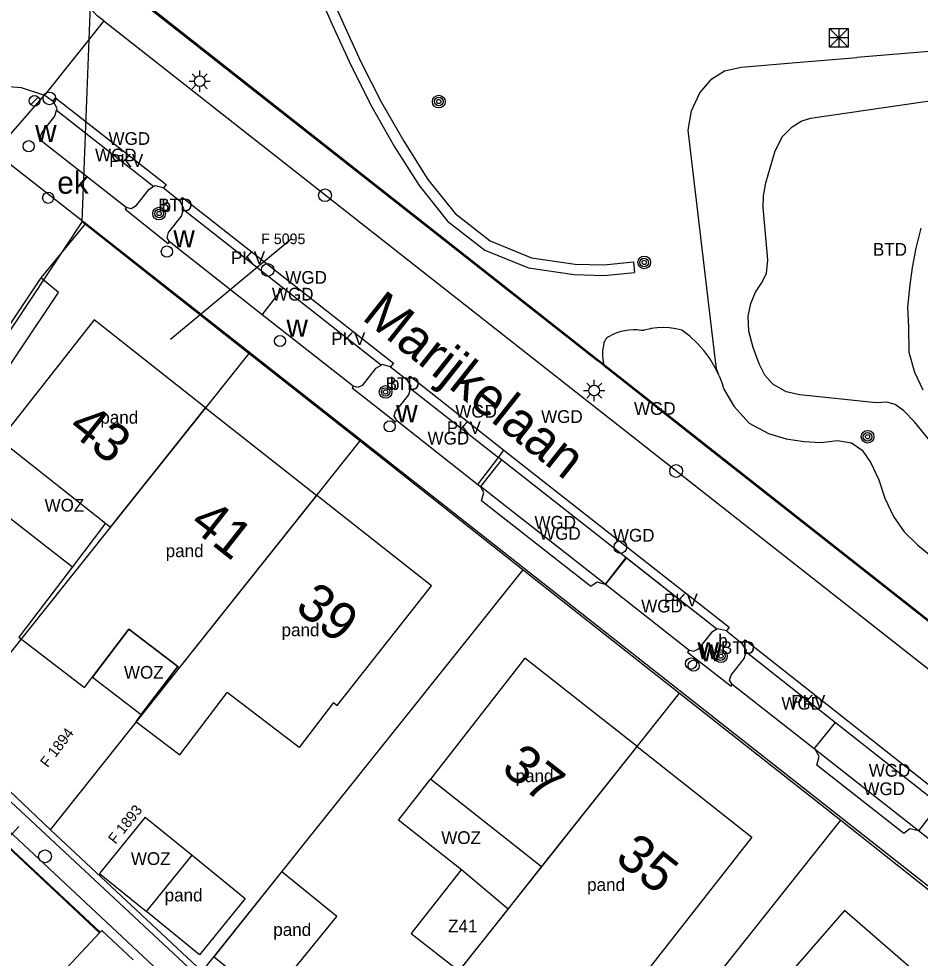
# Model space of a CAD drawing. Extents: x 198240 to 198429, y 356553 to 356721.
# Drawn here: x 198284.19 to 198326.68, y 356585.33 to 356629.62 of the extents above; entities that cross this region are included whole.
import ezdxf

# ---------------------------------------------------------------- set-up
doc = ezdxf.new("R2010")
doc.units = 0
for name, color, linetype in [('Afsluitpaal', 7, 'Continuous'), ('begroeid terreindeel kenmerkpunt', 7, 'Continuous'), ('bijgebouw', 7, 'Continuous'), ('bijpijling', 7, 'Continuous'), ('BOOM', 7, 'Continuous'), ('Elektrakast', 7, 'Continuous'), ('grens individueel parkeervak', 7, 'Continuous'), ('Grens maaiveld', 7, 'Continuous'), ('grens WOZ object', 7, 'Continuous'), ('hoofdgebouw', 7, 'Continuous'), ('huisnummerreeks BGT', 7, 'Continuous'), ('identificerend kenmerkpunt bijpand', 7, 'Continuous'), ('identificerend kenmerkpunt pand', 7, 'Continuous'), ('identificerend kenmerkpunt parkeervak', 7, 'Continuous'), ('identificerend kenmerkpunt WOZ object', 7, 'Continuous'), ('kant verharding', 7, 'Continuous'), ('kolk', 7, 'Continuous'), ('LICHTMAST', 7, 'Continuous'), ('openbare ruimte label tekst', 7, 'Continuous'), ('Perceelnummer', 7, 'Continuous'), ('perceelsgrens_definitief', 7, 'Continuous'), ('schutting geen IMGeo', 7, 'Continuous'), ('Speelvoorziening', 7, 'Continuous'), ('tussenmuur', 7, 'Continuous'), ('tussenmuur bijgebouw (GBKN Zuid)', 7, 'Continuous'), ('vlakafsluiter', 7, 'Continuous'), ('waterleidingput', 7, 'Continuous'), ('wegdeel kenmerkpunt', 7, 'Continuous'), ('weginrichtingselement', 7, 'Continuous'), ('weginrichtingselement lijn', 7, 'Continuous')]:
    doc.layers.add(name, color=color, linetype=linetype)

msp = doc.modelspace()

# ---------------------------------------------------------------- linework, layer by layer
at = {"layer": 'Afsluitpaal'}
msp.add_line((198285.105, 356625.932), (198284.755, 356625.575), dxfattribs=at)
msp.add_circle((198284.932, 356625.752), 0.25, dxfattribs=at)
at = {"layer": 'bijgebouw'}
for p, q in [((198290.208, 356587.525), (198292.365, 356590.18)), ((198307.263, 356587.645), (198305.057, 356589.501)), ((198288.036, 356586.564), (198288.004, 356586.53))]:
    msp.add_line(p, q, dxfattribs=at)
for points in [[(198292.365, 356590.18), (198294.863, 356588.151), (198292.706, 356585.496), (198290.208, 356587.525)], [(198304.895, 356584.747), (198302.686, 356586.482), (198305.057, 356589.501)], [(198293.396, 356585.4), (198295.948, 356583.327), (198299.176, 356587.3), (198296.591, 356589.4)], [(198304.895, 356584.747), (198304.94, 356584.712), (198307.038, 356587.361)], [(198288.004, 356586.53), (198286.046, 356584.433), (198287.524, 356583.052)], [(198289.586, 356585.259), (198288.107, 356586.64), (198288.036, 356586.564)]]:
    msp.add_lwpolyline(points, dxfattribs=at)
at = {"layer": 'bijpijling'}
for points in [[(198291.34, 356614.512), (198297.037, 356619.245)], [(198284.2, 356591.537), (198281.985, 356589.12)]]:
    msp.add_lwpolyline(points, dxfattribs=at)
at = {"layer": 'BOOM'}
for centre, radius in [((198303.989, 356625.719), 0.3), ((198303.989, 356625.719), 0.2), ((198303.989, 356625.719), 0.1), ((198290.807, 356620.438), 0.3), ((198290.807, 356620.438), 0.2), ((198290.807, 356620.438), 0.1), ((198313.67, 356618.133), 0.3), ((198313.67, 356618.133), 0.2), ((198313.67, 356618.133), 0.1), ((198301.481, 356612.027), 0.3), ((198301.481, 356612.027), 0.2), ((198301.481, 356612.027), 0.1), ((198324.194, 356609.914), 0.3), ((198324.194, 356609.914), 0.2), ((198324.194, 356609.914), 0.1), ((198317.286, 356599.569), 0.3), ((198317.286, 356599.569), 0.2), ((198317.286, 356599.569), 0.1)]:
    msp.add_circle(centre, radius, dxfattribs=at)
at = {"layer": 'Elektrakast'}
msp.add_circle((198285.578, 356621.181), 0.263, dxfattribs=at)
msp.add_circle((198285.578, 356621.181), 0.263, dxfattribs=at)
at = {"layer": 'grens individueel parkeervak'}
for p, q in [((198295.667, 356615.664), (198296.651, 356616.938)), ((198305.835, 356607.67), (198306.799, 356608.938)), ((198312.797, 356604.22), (198311.822, 356602.963)), ((198317.094, 356600.839), (198312.797, 356604.22)), ((198321.677, 356595.203), (198322.687, 356596.444)), ((198327.572, 356592.592), (198326.591, 356591.338))]:
    msp.add_line(p, q, dxfattribs=at)
at = {"layer": 'Grens maaiveld'}
for p, q in [((198288.208, 356629.517), (198285.402, 356626.015)), ((198311.777, 356613.258), (198311.48, 356613.492)), ((198317.199, 356612.779), (198317.078, 356613.123)), ((198306.799, 356608.938), (198307.06, 356609.283)), ((198306.942, 356608.825), (198305.958, 356607.573)), ((198306.942, 356608.825), (198306.799, 356608.938)), ((198312.797, 356604.22), (198306.942, 356608.825)), ((198311.849, 356602.941), (198312.832, 356604.192)), ((198312.832, 356604.192), (198312.797, 356604.22)), ((198317.094, 356600.839), (198312.832, 356604.192))]:
    msp.add_line(p, q, dxfattribs=at)
for points in [[(198336.899, 356626.798), (198336.881, 356626.857), (198336.843, 356627.128), (198336.681, 356627.641), (198336.15, 356628.206), (198335.359, 356628.591), (198334.475, 356628.685), (198323.691, 356627.793)], [(198285.813, 356625.732), (198285.921, 356625.893), (198291.141, 356621.811), (198291.01, 356621.645)], [(198291.791, 356621.031), (198291.917, 356621.197), (198301.847, 356613.38), (198301.714, 356613.215)], [(198317.199, 356612.779), (198316.997, 356613.202), (198316.756, 356613.605), (198316.478, 356613.982), (198316.164, 356614.331), (198315.819, 356614.649), (198315.446, 356614.933), (198315.158, 356615.005), (198314.865, 356615.05), (198314.568, 356615.065), (198314.272, 356615.052), (198313.983, 356615.011), (198313.978, 356615.01), (198313.976, 356615.01), (198313.949, 356615.003), (198313.69, 356614.94), (198313.664, 356614.934), (198313.638, 356614.929), (198313.612, 356614.926), (198313.585, 356614.925), (198313.559, 356614.926), (198313.533, 356614.929), (198313.338, 356614.948), (198313.142, 356614.952), (198312.946, 356614.94), (198312.752, 356614.912), (198312.56, 356614.869), (198312.373, 356614.81), (198312.192, 356614.736), (198312.016, 356614.648), (198311.979, 356614.625), (198311.944, 356614.6), (198311.911, 356614.571), (198311.881, 356614.54), (198311.853, 356614.507), (198311.829, 356614.471), (198311.807, 356614.434), (198311.788, 356614.394), (198311.773, 356614.354), (198311.761, 356614.312), (198311.727, 356614.138), (198311.707, 356613.961), (198311.703, 356613.784), (198311.705, 356613.744), (198311.713, 356613.607), (198311.738, 356613.431), (198311.777, 356613.258)], [(198311.777, 356613.258), (198312.501, 356612.688), (198316.479, 356609.557), (198334.051, 356595.726), (198335.895, 356595.044), (198338.762, 356595.561)], [(198302.5, 356612.597), (198302.634, 356612.765), (198307.06, 356609.283)], [(198317.199, 356612.779), (198317.336, 356612.425), (198317.386, 356612.247), (198317.407, 356612.187), (198317.895, 356611.359), (198318.614, 356610.555), (198319.52, 356610.06), (198320.357, 356609.822), (198321.201, 356609.69), (198321.995, 356609.641), (198322.783, 356609.732), (198323.445, 356609.626), (198323.947, 356609.289), (198324.35, 356608.68), (198324.73, 356607.89), (198325.01, 356607.025), (198325.417, 356606.155), (198325.926, 356605.432), (198326.545, 356604.821), (198327.369, 356604.143), (198328.198, 356603.565), (198329.158, 356603.295), (198329.827, 356603.248)], [(198307.06, 356609.283), (198317.674, 356600.934), (198317.546, 356600.763)], [(198318.292, 356600.168), (198318.429, 356600.335), (198329.434, 356591.655)], [(198313.331, 356595.307), (198318.74, 356591.044), (198314.299, 356585.364), (198312.495, 356583.057)], [(198328.26, 356583.099), (198323.101, 356587.58), (198317.022, 356580.581)]]:
    msp.add_lwpolyline(points, dxfattribs=at)
at = {"layer": 'grens WOZ object'}
for p, q in [((198283.799, 356606.053), (198286.719, 356603.776)), ((198289.384, 356600.837), (198287.66, 356598.573)), ((198291.689, 356599.081), (198289.384, 356600.837)), ((198289.966, 356596.817), (198291.689, 356599.081)), ((198287.66, 356598.573), (198289.966, 356596.817)), ((198302.092, 356591.83), (198303.592, 356593.774)), ((198290.157, 356591.974), (198288, 356589.319)), ((198290.157, 356591.974), (198292.365, 356590.18)), ((198305.057, 356589.501), (198302.092, 356591.83)), ((198307.263, 356587.645), (198308.835, 356589.63)), ((198288, 356589.319), (198290.208, 356587.525))]:
    msp.add_line(p, q, dxfattribs=at)
at = {"layer": 'hoofdgebouw'}
for p, q in [((198287.746, 356615.433), (198283.304, 356609.78)), ((198293.001, 356611.274), (198287.746, 356615.433)), ((198293.001, 356611.274), (198298.237, 356607.149)), ((198283.398, 356609.706), (198288.287, 356605.835)), ((198288.287, 356605.835), (198286.719, 356603.776)), ((198308.835, 356589.63), (198303.592, 356593.774)), ((198307.038, 356587.361), (198307.263, 356587.645))]:
    msp.add_line(p, q, dxfattribs=at)
for points in [[(198299.019, 356597.382), (198299.195, 356597.243), (198303.641, 356602.893), (198298.237, 356607.149)], [(198286.719, 356603.776), (198284.195, 356600.459), (198287.298, 356598.097), (198289.384, 356600.837), (198291.689, 356599.081)], [(198313.331, 356595.307), (198308.042, 356599.476), (198303.592, 356593.774)], [(198291.689, 356599.081), (198289.712, 356596.484), (198291.776, 356594.912), (198294.017, 356597.856)], [(198299.019, 356597.382), (198297.412, 356595.271), (198294.017, 356597.856)]]:
    msp.add_lwpolyline(points, dxfattribs=at)
at = {"layer": 'kant verharding'}
for p, q in [((198288.208, 356629.517), (198332.081, 356595.014)), ((198320.826, 356627.555), (198323.691, 356627.793)), ((198285.978, 356625.317), (198290.565, 356621.72)), ((198287.334, 356619.961), (198283.058, 356623.324)), ((198291.01, 356621.645), (198291.791, 356621.031)), ((198291.956, 356620.634), (198296.651, 356616.938)), ((198295.667, 356615.664), (198291.298, 356619.105)), ((198313.171, 356618.156), (198313.219, 356617.658)), ((198285.231, 356617.401), (198277.829, 356606.337)), ((198296.651, 356616.938), (198301.281, 356613.294)), ((198299.953, 356612.296), (198295.667, 356615.664)), ((198317.078, 356613.123), (198316.972, 356614.011)), ((198301.714, 356613.215), (198302.5, 356612.597)), ((198302.661, 356612.193), (198306.799, 356608.938)), ((198302.003, 356610.682), (198305.835, 356607.67)), ((198305.835, 356607.67), (198305.958, 356607.573)), ((198311.822, 356602.963), (198305.958, 356607.573)), ((198311.849, 356602.941), (198311.822, 356602.963)), ((198315.775, 356599.854), (198311.849, 356602.941)), ((198317.546, 356600.763), (198318.292, 356600.168)), ((198318.467, 356599.771), (198322.687, 356596.444)), ((198321.677, 356595.203), (198317.813, 356598.241)), ((198322.687, 356596.444), (198327.572, 356592.592)), ((198321.742, 356595.152), (198321.677, 356595.203)), ((198326.591, 356591.338), (198321.742, 356595.152)), ((198288.036, 356586.564), (198281.792, 356592.387))]:
    msp.add_line(p, q, dxfattribs=at)
for points in [[(198296.093, 356639.541), (198296.614, 356637.469), (198297.244, 356635.408), (198297.875, 356633.478), (198298.543, 356631.541), (198299.422, 356629.562), (198300.306, 356627.615), (198301.275, 356625.709), (198302.334, 356623.845), (198303.469, 356622.044), (198304.754, 356620.44), (198306.413, 356619.147), (198308.355, 356618.357), (198310.417, 356618.058), (198311.77, 356618.022), (198313.171, 356618.156)], [(198295.609, 356639.419), (198296.132, 356637.335), (198296.768, 356635.258), (198297.401, 356633.318), (198298.077, 356631.357), (198298.966, 356629.358), (198299.856, 356627.399), (198300.835, 356625.473), (198301.904, 356623.589), (198303.061, 356621.754), (198304.4, 356620.082), (198306.161, 356618.711), (198308.223, 356617.871), (198310.375, 356617.558), (198311.788, 356617.522), (198313.219, 356617.658)], [(198288.971, 356634.577), (198289.364, 356630.899), (198311.48, 356613.492)], [(198288.208, 356629.517), (198287.888, 356629.764), (198286.69, 356631.104)], [(198316.972, 356614.011), (198315.738, 356624.363), (198315.902, 356625.288), (198316.294, 356626.134), (198316.86, 356626.789), (198317.445, 356627.16), (198318.234, 356627.341), (198320.826, 356627.555)], [(198276.992, 356622.565), (198277.573, 356623.379), (198278.532, 356624.618), (198279.766, 356625.596), (198281.202, 356626.245), (198282.742, 356626.511), (198284.311, 356626.387), (198285.402, 356626.015)], [(198328.604, 356607.922), (198326.409, 356610.623), (198325.909, 356611.138), (198325.493, 356611.442), (198325.108, 356611.541), (198324.608, 356611.514), (198321.006, 356611.885), (198320.366, 356612.034), (198319.737, 356612.396), (198319.36, 356612.819), (198319.085, 356613.357), (198318.805, 356614.123), (198318.597, 356614.899), (198318.572, 356615.606), (198318.689, 356616.203), (198318.912, 356616.736), (198319.202, 356617.152), (198319.428, 356617.606), (198319.492, 356618.251), (198319.276, 356620.725), (198319.293, 356621.271), (198319.393, 356621.886), (198319.84, 356623.388), (198320.192, 356624.068), (198320.645, 356624.527), (198321.07, 356624.786), (198321.505, 356624.931), (198331.116, 356626.341)], [(198285.402, 356626.015), (198285.436, 356626.003), (198285.813, 356625.732)], [(198285.978, 356625.317), (198285.999, 356625.388), (198285.813, 356625.732)], [(198289.258, 356620.725), (198285.329, 356623.81), (198285.205, 356624.035), (198285.28, 356624.25), (198285.893, 356625.035), (198285.978, 356625.317)], [(198290.565, 356621.72), (198290.294, 356621.546), (198289.676, 356620.767), (198289.487, 356620.655), (198289.258, 356620.725)], [(198291.01, 356621.645), (198290.602, 356621.744), (198290.565, 356621.72)], [(198291.956, 356620.634), (198291.971, 356620.683), (198291.791, 356621.031)], [(198289.258, 356620.725), (198289.201, 356620.65), (198291.24, 356619.027), (198291.298, 356619.105)], [(198291.298, 356619.105), (198291.187, 356619.298), (198291.246, 356619.537), (198291.857, 356620.314), (198291.956, 356620.634)], [(198358.681, 356553.702), (198344.512, 356570.974), (198344.626, 356571.073), (198339.557, 356577.216), (198339.341, 356577.012), (198337.792, 356578.849), (198336.463, 356580.312), (198334.882, 356581.942), (198333.211, 356583.577), (198331.471, 356585.153), (198329.894, 356586.497), (198328.385, 356587.677), (198287.334, 356619.961)], [(198326.707, 356619.748), (198326.472, 356618.803), (198326.29, 356617.9), (198326.192, 356617.072), (198326.085, 356616.03), (198326.122, 356615.092), (198326.137, 356613.896), (198326.409, 356612.966), (198326.8, 356612.127)], [(198278.665, 356605.666), (198286.066, 356616.715), (198285.231, 356617.401)], [(198301.281, 356613.294), (198301.001, 356613.136), (198300.372, 356612.336), (198300.174, 356612.232), (198299.953, 356612.296)], [(198301.714, 356613.215), (198301.32, 356613.316), (198301.281, 356613.294)], [(198302.661, 356612.193), (198302.691, 356612.298), (198302.5, 356612.597)], [(198299.953, 356612.296), (198299.909, 356612.223), (198301.949, 356610.616), (198302.003, 356610.682)], [(198302.003, 356610.682), (198301.888, 356610.888), (198301.944, 356611.103), (198302.573, 356611.884), (198302.661, 356612.193)], [(198311.849, 356602.941), (198311.455, 356603.056), (198311.153, 356602.854), (198306.008, 356606.896), (198306.118, 356607.288), (198305.958, 356607.573)], [(198317.094, 356600.839), (198316.834, 356600.682), (198316.209, 356599.904), (198315.99, 356599.785), (198315.775, 356599.854)], [(198317.546, 356600.763), (198317.13, 356600.861), (198317.094, 356600.839)], [(198318.467, 356599.771), (198318.486, 356599.833), (198318.292, 356600.168)], [(198315.775, 356599.854), (198315.709, 356599.763), (198317.765, 356598.158), (198317.813, 356598.241)], [(198317.813, 356598.241), (198317.696, 356598.434), (198317.762, 356598.678), (198318.373, 356599.455), (198318.467, 356599.771)], [(198322.703, 356553.702), (198305.854, 356572.145), (198276.632, 356599.402)], [(198326.591, 356591.338), (198326.191, 356591.427), (198325.902, 356591.215), (198321.812, 356594.434), (198321.922, 356594.842), (198321.742, 356595.152)], [(198330.793, 356588.001), (198329.743, 356588.86), (198326.591, 356591.338)]]:
    msp.add_lwpolyline(points, dxfattribs=at)
at = {"layer": 'kolk'}
for centre in [(198285.637, 356625.865), (198298.626, 356621.299), (198295.926, 356617.775), (198315.174, 356608.3), (198312.549, 356604.715), (198285.43, 356590.132)]:
    msp.add_circle(centre, 0.3, dxfattribs=at)
at = {"layer": 'LICHTMAST'}
for p, q in [((198292.721, 356626.928), (198292.721, 356627.178)), ((198292.221, 356626.678), (198292.471, 356626.678)), ((198292.544, 356626.855), (198292.367, 356627.032)), ((198292.898, 356626.855), (198293.075, 356627.032)), ((198292.971, 356626.678), (198293.221, 356626.678)), ((198292.367, 356626.324), (198292.544, 356626.501)), ((198292.721, 356626.178), (198292.721, 356626.428)), ((198293.075, 356626.324), (198292.898, 356626.501)), ((198311.311, 356612.344), (198311.311, 356612.594)), ((198310.811, 356612.094), (198311.061, 356612.094)), ((198311.134, 356612.271), (198310.957, 356612.448)), ((198311.488, 356612.271), (198311.665, 356612.448)), ((198311.561, 356612.094), (198311.811, 356612.094)), ((198310.957, 356611.74), (198311.134, 356611.917)), ((198311.311, 356611.594), (198311.311, 356611.844)), ((198311.665, 356611.74), (198311.488, 356611.917))]:
    msp.add_line(p, q, dxfattribs=at)
for centre in [(198292.721, 356626.678), (198311.311, 356612.094)]:
    msp.add_circle(centre, 0.25, dxfattribs=at)
at = {"layer": 'perceelsgrens_definitief'}
for points in [[(198287.174, 356620.057), (198287.646, 356632.339)], [(198287.646, 356632.339), (198335.086, 356594.965)], [(198287.174, 356620.057), (198274.894, 356601.537), (198276.811, 356599.792)], [(198287.174, 356620.057), (198290.05, 356617.789)], [(198290.05, 356617.789), (198295.051, 356613.842)], [(198280.812, 356596.003), (198295.051, 356613.842)], [(198295.051, 356613.842), (198300.278, 356609.715)], [(198285.695, 356591.384), (198300.278, 356609.715)], [(198300.278, 356609.715), (198307.969, 356603.645)], [(198292.841, 356584.705), (198307.969, 356603.645)], [(198307.969, 356603.645), (198315.332, 356597.833)], [(198275.847, 356598.687), (198293.958, 356581.762), (198299.047, 356577.045), (198300.934, 356575.281), (198303.1, 356573.036), (198305.083, 356571.014), (198307.527, 356568.392), (198311.848, 356563.616), (198317.236, 356557.707), (198320.88, 356553.702)], [(198299.785, 356578.205), (198315.332, 356597.833)], [(198315.332, 356597.833), (198322.937, 356591.83)], [(198280.812, 356596.003), (198285.695, 356591.384)], [(198306.788, 356571.509), (198322.937, 356591.83)], [(198322.937, 356591.83), (198327.497, 356588.229)], [(198285.695, 356591.384), (198292.841, 356584.705)]]:
    msp.add_lwpolyline(points, dxfattribs=at)
at = {"layer": 'schutting geen IMGeo'}
msp.add_line((198288.004, 356586.53), (198281.768, 356592.361), dxfattribs=at)
at = {"layer": 'Speelvoorziening'}
for p, q in [((198322.399, 356629.157), (198323.279, 356629.157)), ((198322.399, 356628.277), (198322.399, 356629.157)), ((198322.399, 356629.157), (198323.279, 356628.277)), ((198322.399, 356628.277), (198323.279, 356629.157)), ((198322.839, 356629.157), (198322.839, 356628.277)), ((198323.279, 356629.157), (198323.279, 356628.277)), ((198323.279, 356628.717), (198322.399, 356628.717)), ((198323.279, 356628.277), (198322.399, 356628.277))]:
    msp.add_line(p, q, dxfattribs=at)
at = {"layer": 'tussenmuur'}
msp.add_line((198308.835, 356589.63), (198313.331, 356595.307), dxfattribs=at)
for points in [[(198288.287, 356605.835), (198288.516, 356605.655), (198293.001, 356611.274)], [(198291.689, 356599.081), (198291.769, 356599.02), (198298.237, 356607.149)]]:
    msp.add_lwpolyline(points, dxfattribs=at)
at = {"layer": 'tussenmuur bijgebouw (GBKN Zuid)'}
msp.add_line((198293.396, 356585.4), (198296.591, 356589.4), dxfattribs=at)
at = {"layer": 'vlakafsluiter'}
for p, q in [((198283.058, 356623.324), (198285.402, 356626.015)), ((198287.334, 356619.961), (198285.231, 356617.401))]:
    msp.add_line(p, q, dxfattribs=at)
at = {"layer": 'waterleidingput'}
for centre in [(198284.66, 356623.612), (198284.66, 356623.612), (198291.173, 356618.646), (198291.173, 356618.646), (198296.502, 356614.431), (198296.502, 356614.431), (198301.675, 356610.402), (198301.675, 356610.402), (198315.874, 356599.222), (198315.874, 356599.222), (198316, 356599.123), (198316, 356599.123)]:
    msp.add_circle(centre, 0.263, dxfattribs=at)
at = {"layer": 'weginrichtingselement lijn'}
for points in [[(198285.813, 356625.732), (198285.921, 356625.893), (198291.141, 356621.811), (198291.01, 356621.645)], [(198291.791, 356621.031), (198291.917, 356621.197), (198301.847, 356613.38), (198301.714, 356613.215)], [(198302.5, 356612.597), (198302.634, 356612.765), (198307.06, 356609.283)], [(198307.06, 356609.283), (198317.674, 356600.934), (198317.546, 356600.763)], [(198318.292, 356600.168), (198318.429, 356600.335), (198329.434, 356591.655)]]:
    msp.add_lwpolyline(points, dxfattribs=at)

# ---------------------------------------------------------------- texts
at = {"layer": 'begroeid terreindeel kenmerkpunt'}
for p in [(198290.773, 356620.543), (198324.449, 356618.447), (198301.481, 356612.123), (198317.284, 356599.67)]:
    msp.add_text('BTD', height=0.6, dxfattribs=at).set_placement(p)
at = {"layer": 'Elektrakast'}
msp.add_text('ek', height=1.05, dxfattribs=at).set_placement((198286.007, 356621.372))
at = {"layer": 'huisnummerreeks BGT'}
for s, rotation, p in [('43', 321.6, (198286.441, 356610.217)), ('41', 321.8, (198292.171, 356605.69)), ('39', 321.8, (198297.15, 356601.768)), ('37', 321.8, (198306.868, 356594.161)), ('35', 321.8, (198312.231, 356589.935))]:
    msp.add_text(s, height=1.8, rotation=rotation, dxfattribs=at).set_placement(p)
at = {"layer": 'identificerend kenmerkpunt bijpand'}
for s, p in [('pand', (198291.069, 356588.007)), ('pand', (198296.188, 356586.38)), ('Z41', (198304.424, 356586.546))]:
    msp.add_text(s, height=0.6, dxfattribs=at).set_placement(p)
at = {"layer": 'identificerend kenmerkpunt pand'}
for p in [(198288.038, 356610.53), (198291.118, 356604.24), (198296.578, 356600.51), (198307.608, 356593.63), (198310.978, 356588.5)]:
    msp.add_text('pand', height=0.6, dxfattribs=at).set_placement(p)
at = {"layer": 'identificerend kenmerkpunt parkeervak'}
for p in [(198288.453, 356622.638), (198294.198, 356618.057), (198298.919, 356614.234), (198304.367, 356610.044), (198314.591, 356601.921), (198320.601, 356597.144)]:
    msp.add_text('PKV', height=0.6, dxfattribs=at).set_placement(p)
at = {"layer": 'identificerend kenmerkpunt WOZ object'}
for p in [(198285.41, 356606.386), (198289.149, 356598.509), (198304.103, 356590.715), (198289.475, 356589.725)]:
    msp.add_text('WOZ', height=0.6, dxfattribs=at).set_placement(p)
at = {"layer": 'openbare ruimte label tekst'}
msp.add_text('Marijkelaan', height=1.8, rotation=321.6, dxfattribs=at).set_placement((198300.312, 356615.483))
at = {"layer": 'Perceelnummer'}
msp.add_text('F 5095', height=0.5, dxfattribs=at).set_placement((198295.62, 356618.995))
for s, rotation, p in [('F 1894', 52.8, (198285.558, 356594.285)), ('F 1893', 51.5, (198288.752, 356590.676))]:
    msp.add_text(s, height=0.5, rotation=rotation, dxfattribs=at).set_placement(p)
at = {"layer": 'waterleidingput'}
for p in [(198284.964, 356623.81), (198291.477, 356618.844), (198296.806, 356614.629), (198301.979, 356610.6), (198316.178, 356599.42), (198316.304, 356599.321)]:
    msp.add_text('w', height=1.05, dxfattribs=at).set_placement(p)
at = {"layer": 'wegdeel kenmerkpunt'}
for p in [(198288.421, 356623.676), (198287.787, 356622.898), (198296.753, 356617.127), (198296.122, 356616.336), (198304.765, 356610.817), (198308.809, 356610.567), (198313.188, 356610.947), (198303.458, 356609.548), (198308.495, 356605.583), (198308.715, 356605.059), (198312.193, 356604.971), (198313.527, 356601.631), (198320.135, 356597.049), (198324.251, 356593.887), (198324, 356593.018)]:
    msp.add_text('WGD', height=0.6, dxfattribs=at).set_placement(p)
at = {"layer": 'weginrichtingselement'}
for p in [(198290.924, 356620.509), (198301.687, 356612.121), (198317.159, 356600.005)]:
    msp.add_text('b', height=0.6, rotation=0.2905, dxfattribs=at).set_placement(p)

doc.saveas('drawing.dxf')
